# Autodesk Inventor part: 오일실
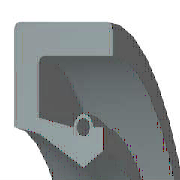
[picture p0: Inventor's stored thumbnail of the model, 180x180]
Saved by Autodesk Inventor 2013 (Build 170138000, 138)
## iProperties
IsCustomPart: 1
Company: 한국ATC센터
Created: 2014-11
Part Number: 오일실
Material: 고무
Description: 오일-실
Document SubType Name: Modeling
Standard: KS B 2804
Designer: KYOUNG IL JANG
Standards Organization: KS
Language: ko-KR
Size Designation: S - 25 40 8
Categories: <MemberInstance><Categories><Category DisplayName="샤프트 부품" InternalName="7f7aeb1f-a693-4053-b835-cee3144e0d98" Mnemonic="SHFT"><Category DisplayName="실링" Intern
Density: 0.93 g/cm^3
Mass: 2.48215 g
Surface Area: 40.3381 cm^2
Volume: 2.66898 cm^3
Author: KYOUNG IL JANG
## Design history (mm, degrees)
revolve "본체" stored, may be unused: angle "d17" = 90 deg
revolve "스프링1" stored, may be unused: angle "d18" = 90 deg
body "Solid1"
sketch "스케치1"
  geometry: L1 (0, 20)-(8, 20); L2 (8, 20)-(8, 18.75); L3 (8, 18.75)-(1.75, 18.75); L4 (0, 20)-(0, 14.6); L5 (0, 14.6)-(1.75, 14.25); L6 (1.75, 14.25)-(4.9, 12.5); L7 (4.9, 12.5)-(0, 12.5); L8 (6.3, 13.375)-(6.3, 14.6); L9 (0, 0)-(9.586, 0) reference; L10 (4.9, 12.5)-(6.3, 13.375); L11 (0, 18)-(0, -3) reference; L12 (-1.917, 0)-(11.503, 0) reference; L13 (4.2, 14.6)-(1.75, 15.09); L14 (1.75, 15.09)-(1.75, 18.75); L15 (6.3, 14.6)-(5.6, 14.6); C1 r 0.455 at (4.9, 14.6); A1 r 0.7 centre (4.9, 14.6) between (5.6, 14.6) and (4.2, 14.6)
  constraints: 26 end point, 5 horizontal alignment, 4 perpendicular, 2 centre point, 2 collinear, 2 horizontal, 2 parallel, 2 point on circle, 2 point on line, 2 vertical alignment, 1 coincident
  dimensions: "d0" = 40 diameter of L1 L9 (= SD2); "d1" = 26.75 diameter of L8.start L9 (= ABDM); "d2" = 1.25 distance of L1.end L2.end (computed from SD); "d3" = 0.91 diameter of C1 (= SPDI); "d4" = 1.4 diameter of A1 (= SPDA); "d5" = 25 diameter of L6.end L9 (= NND); "d6" = 28.5 diameter of L5.end L9 (= TKDM); "d7" = 29.2 diameter of L4.end L9 (= HLDM); "d8" = 4.9 distance from line of C1.centre L4 (= SPDST); "d9" = 6.3 distance between parallel lines of L8 L4 (= SDI); "d10" = 8 distance between parallel lines of L2 L4 (= SWDT); "d12" = 1.75 distance between parallel lines of L14 L4 (= SD)
fillet "모깎기1" dims "d11" = 0.3 (= RR)
other parameters: "SD2" = 40 [user parameter; used in 1 equation term], "SWDT" = 8 [user parameter; used in 1 equation term], "RR" = 0.3 [user parameter; used in 1 equation term], "SD" = 1.75 [user parameter; used in 2 equation terms], "NND" = 25 [user parameter; used in 1 equation term], "SPDA" = 1.4 [user parameter; used in 1 equation term], "SPDI" = 0.91 [user parameter; used in 1 equation term], "TKDM" = 28.5 [user parameter; used in 1 equation term], "HLDM" = 29.2 [user parameter; used in 1 equation term], "ABDM" = 26.75 [user parameter; used in 1 equation term], "SDI" = 6.3 [user parameter; used in 1 equation term], "SPDST" = 4.9 [user parameter; used in 1 equation term], "d13" = 0, "d14" = 0, "d15" = 0, "LAB" = 0.35 [user parameter]
